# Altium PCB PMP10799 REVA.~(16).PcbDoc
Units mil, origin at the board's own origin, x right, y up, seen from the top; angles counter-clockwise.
Board outline 1968.5 x 1968.5 mil, 4 copper layers (Top Layer, Signal Layer 1, Signal Layer 2, Bottom Layer), stack 85.4 mil thick; 51 components, 27 nets, 127 pads, 65 vias.
Unrouted connection lines stored in the file: 1.
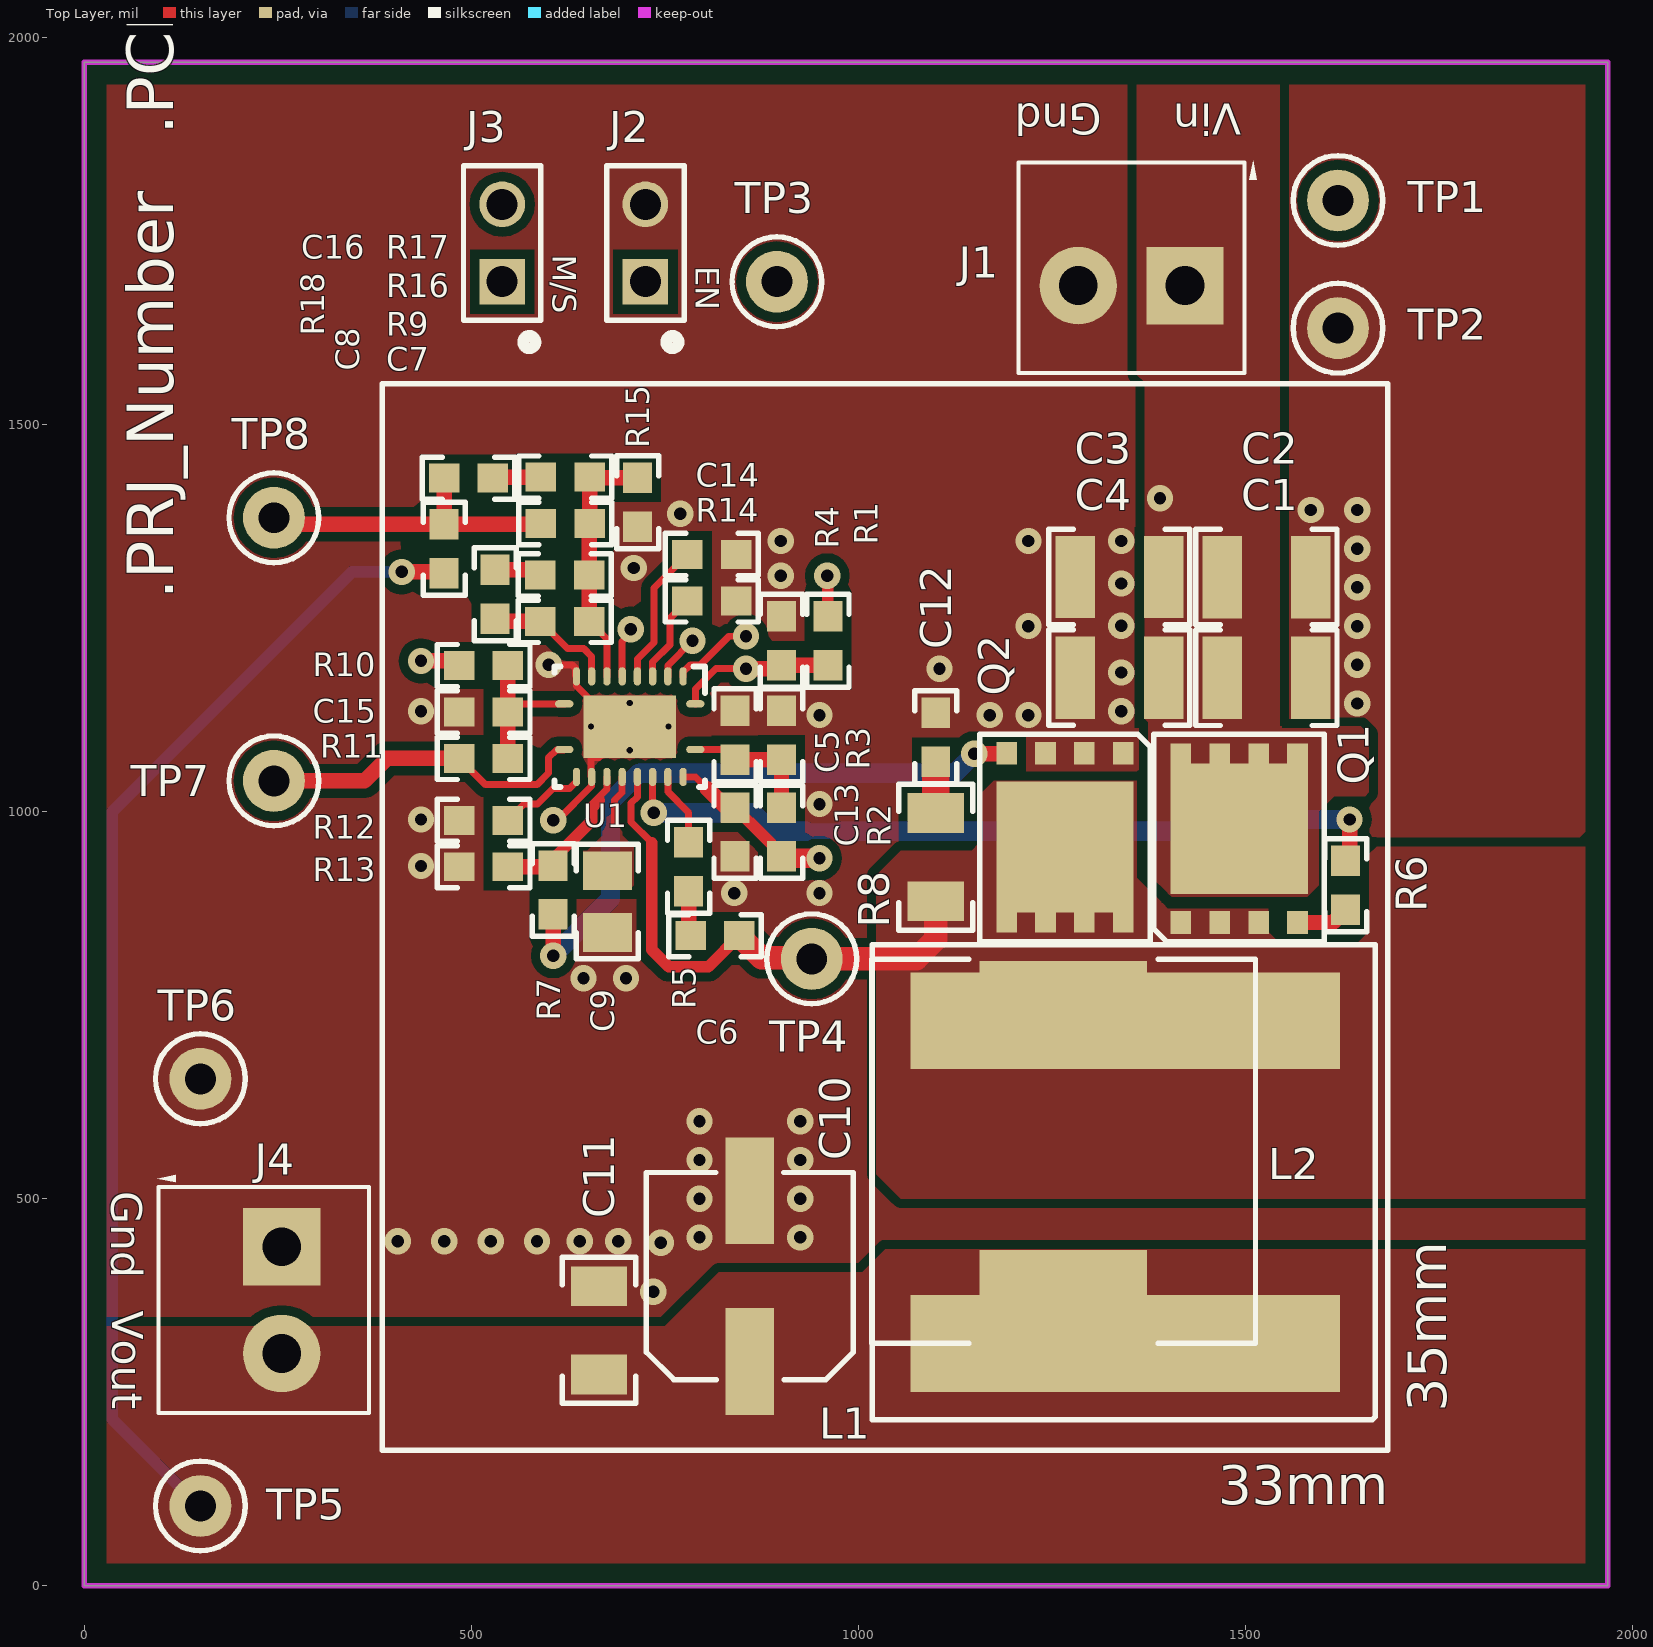
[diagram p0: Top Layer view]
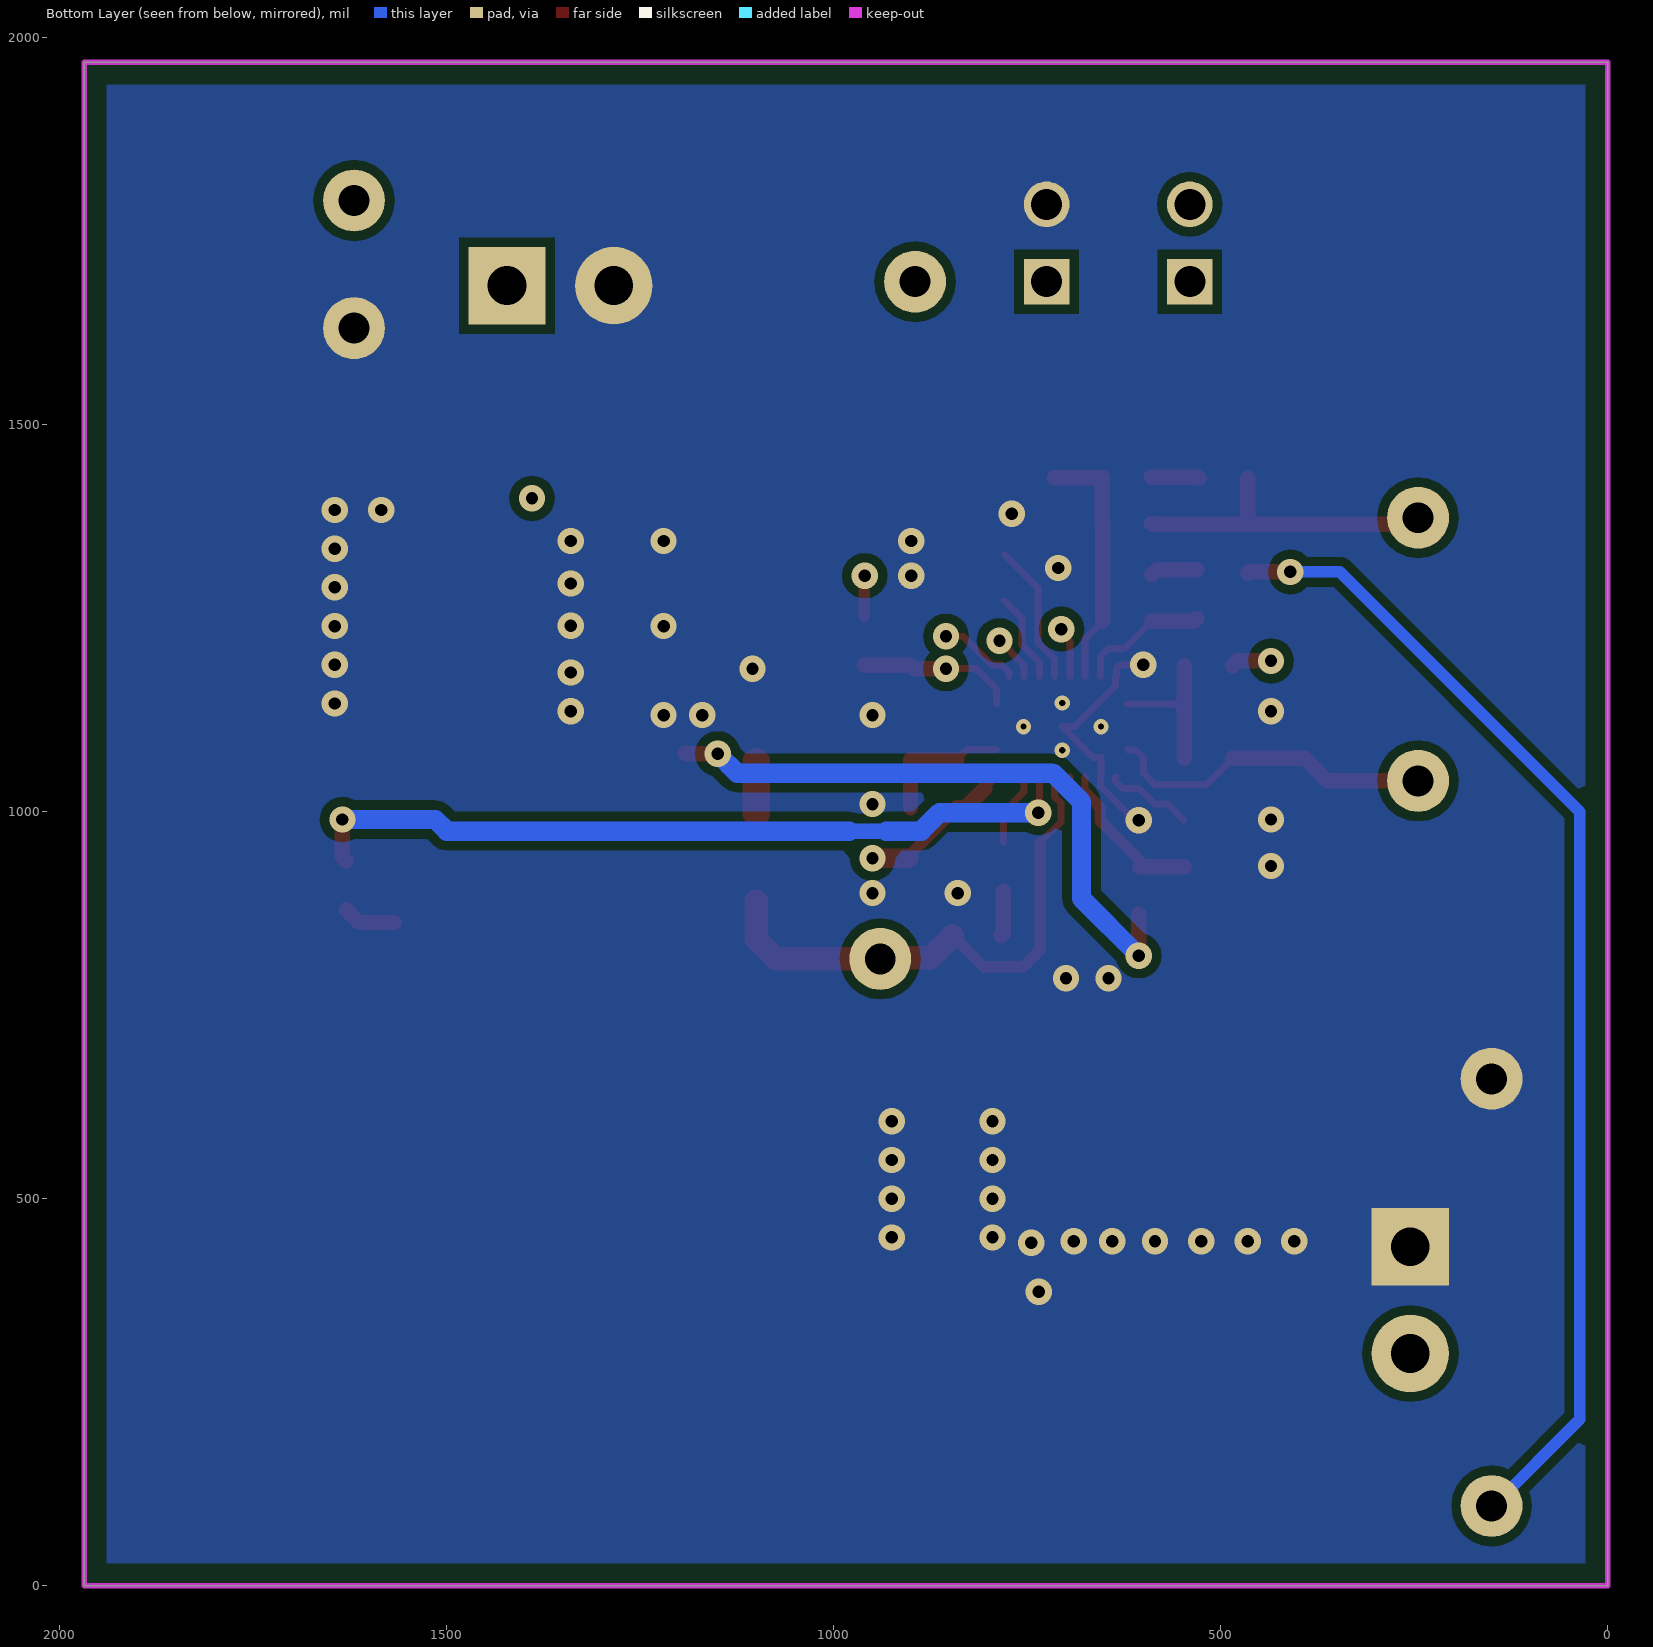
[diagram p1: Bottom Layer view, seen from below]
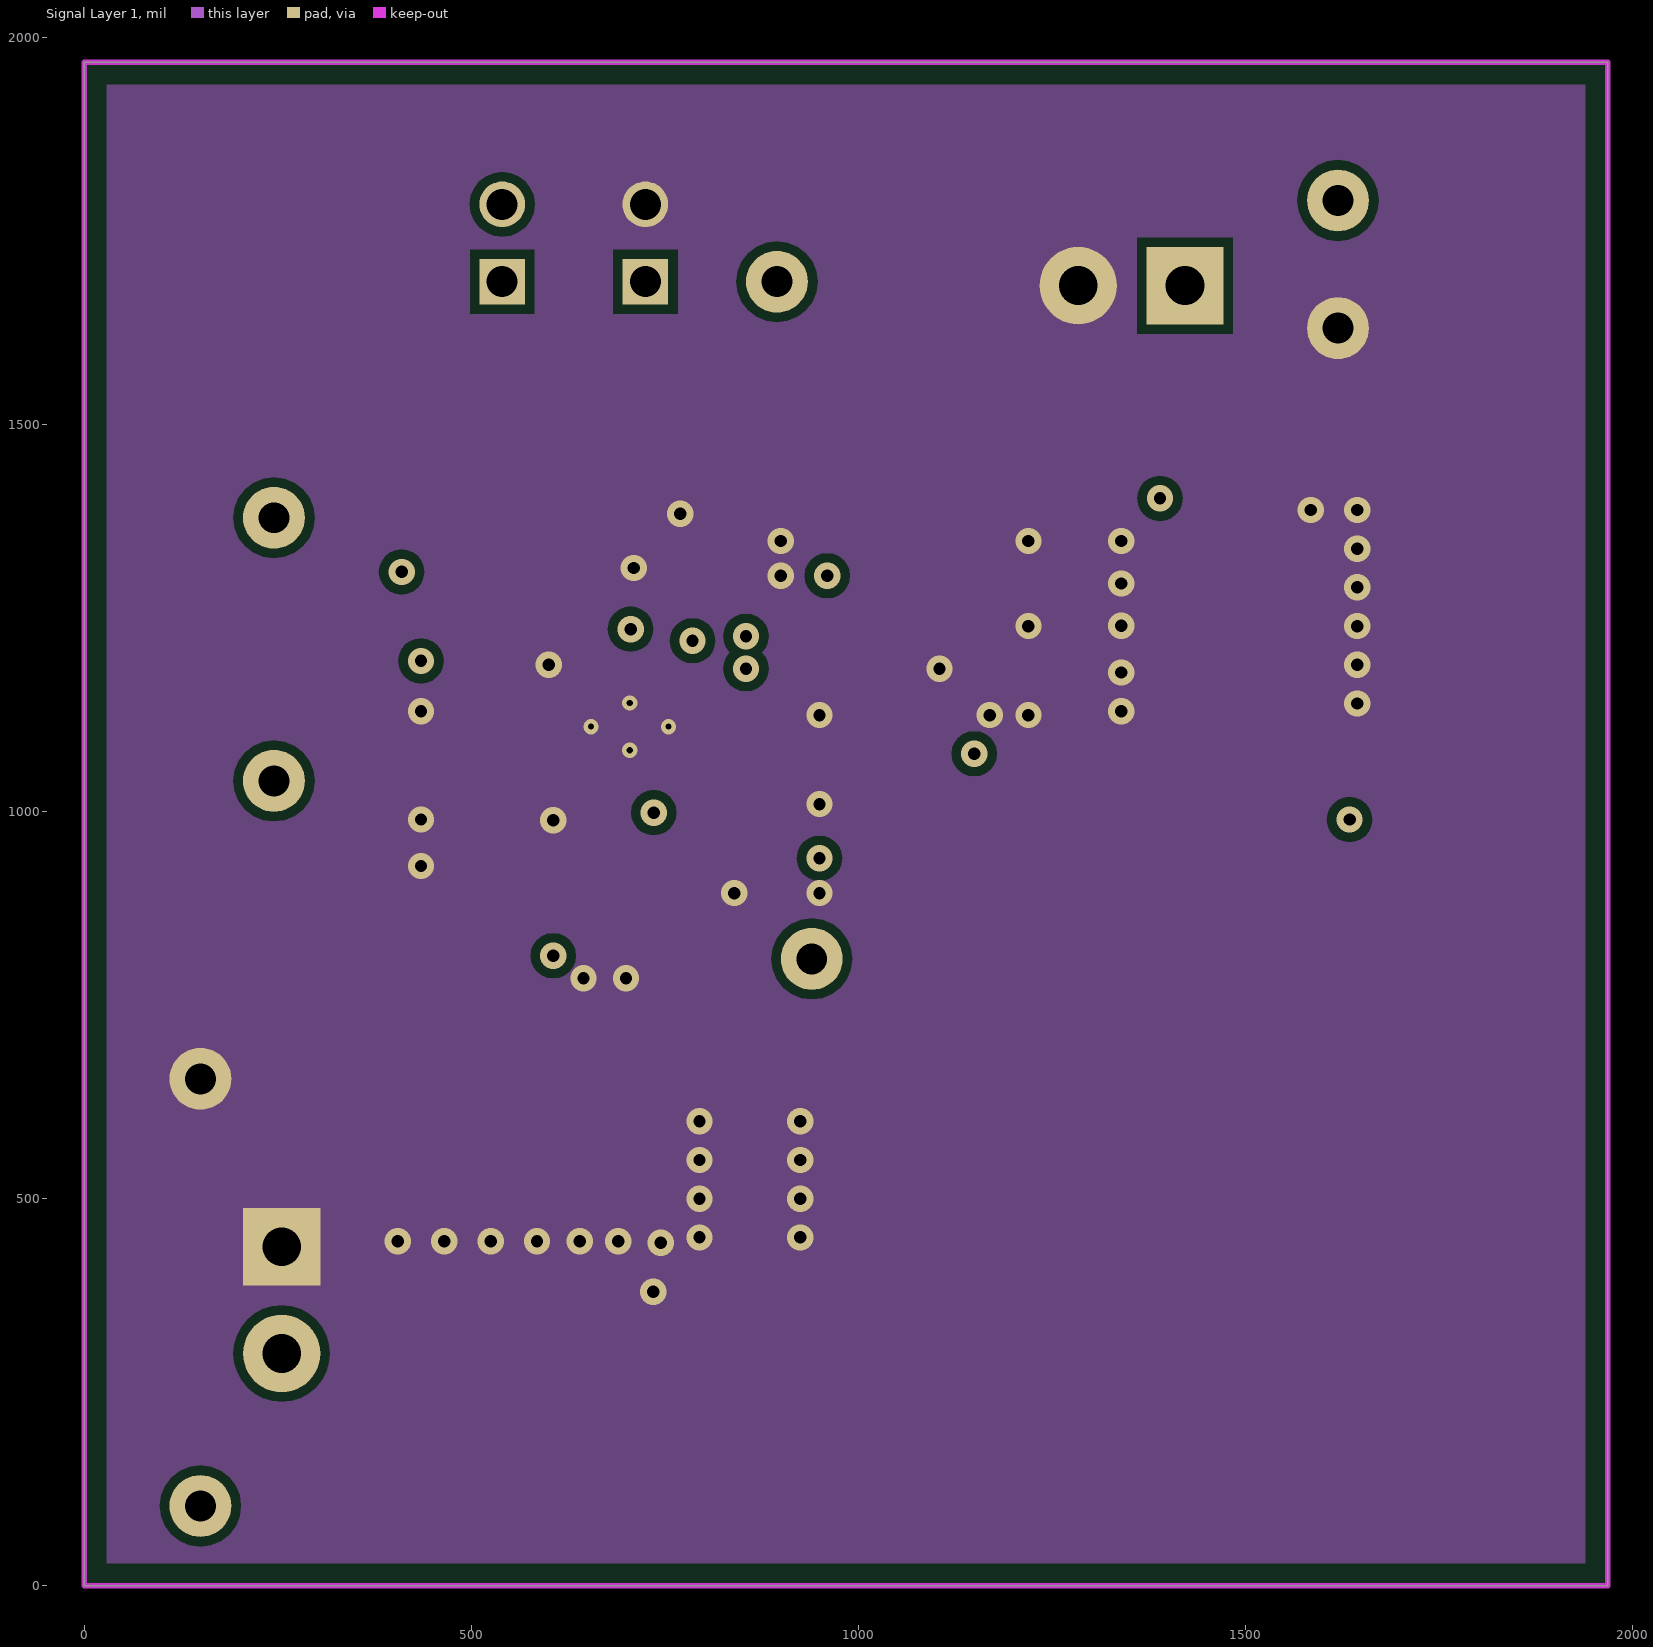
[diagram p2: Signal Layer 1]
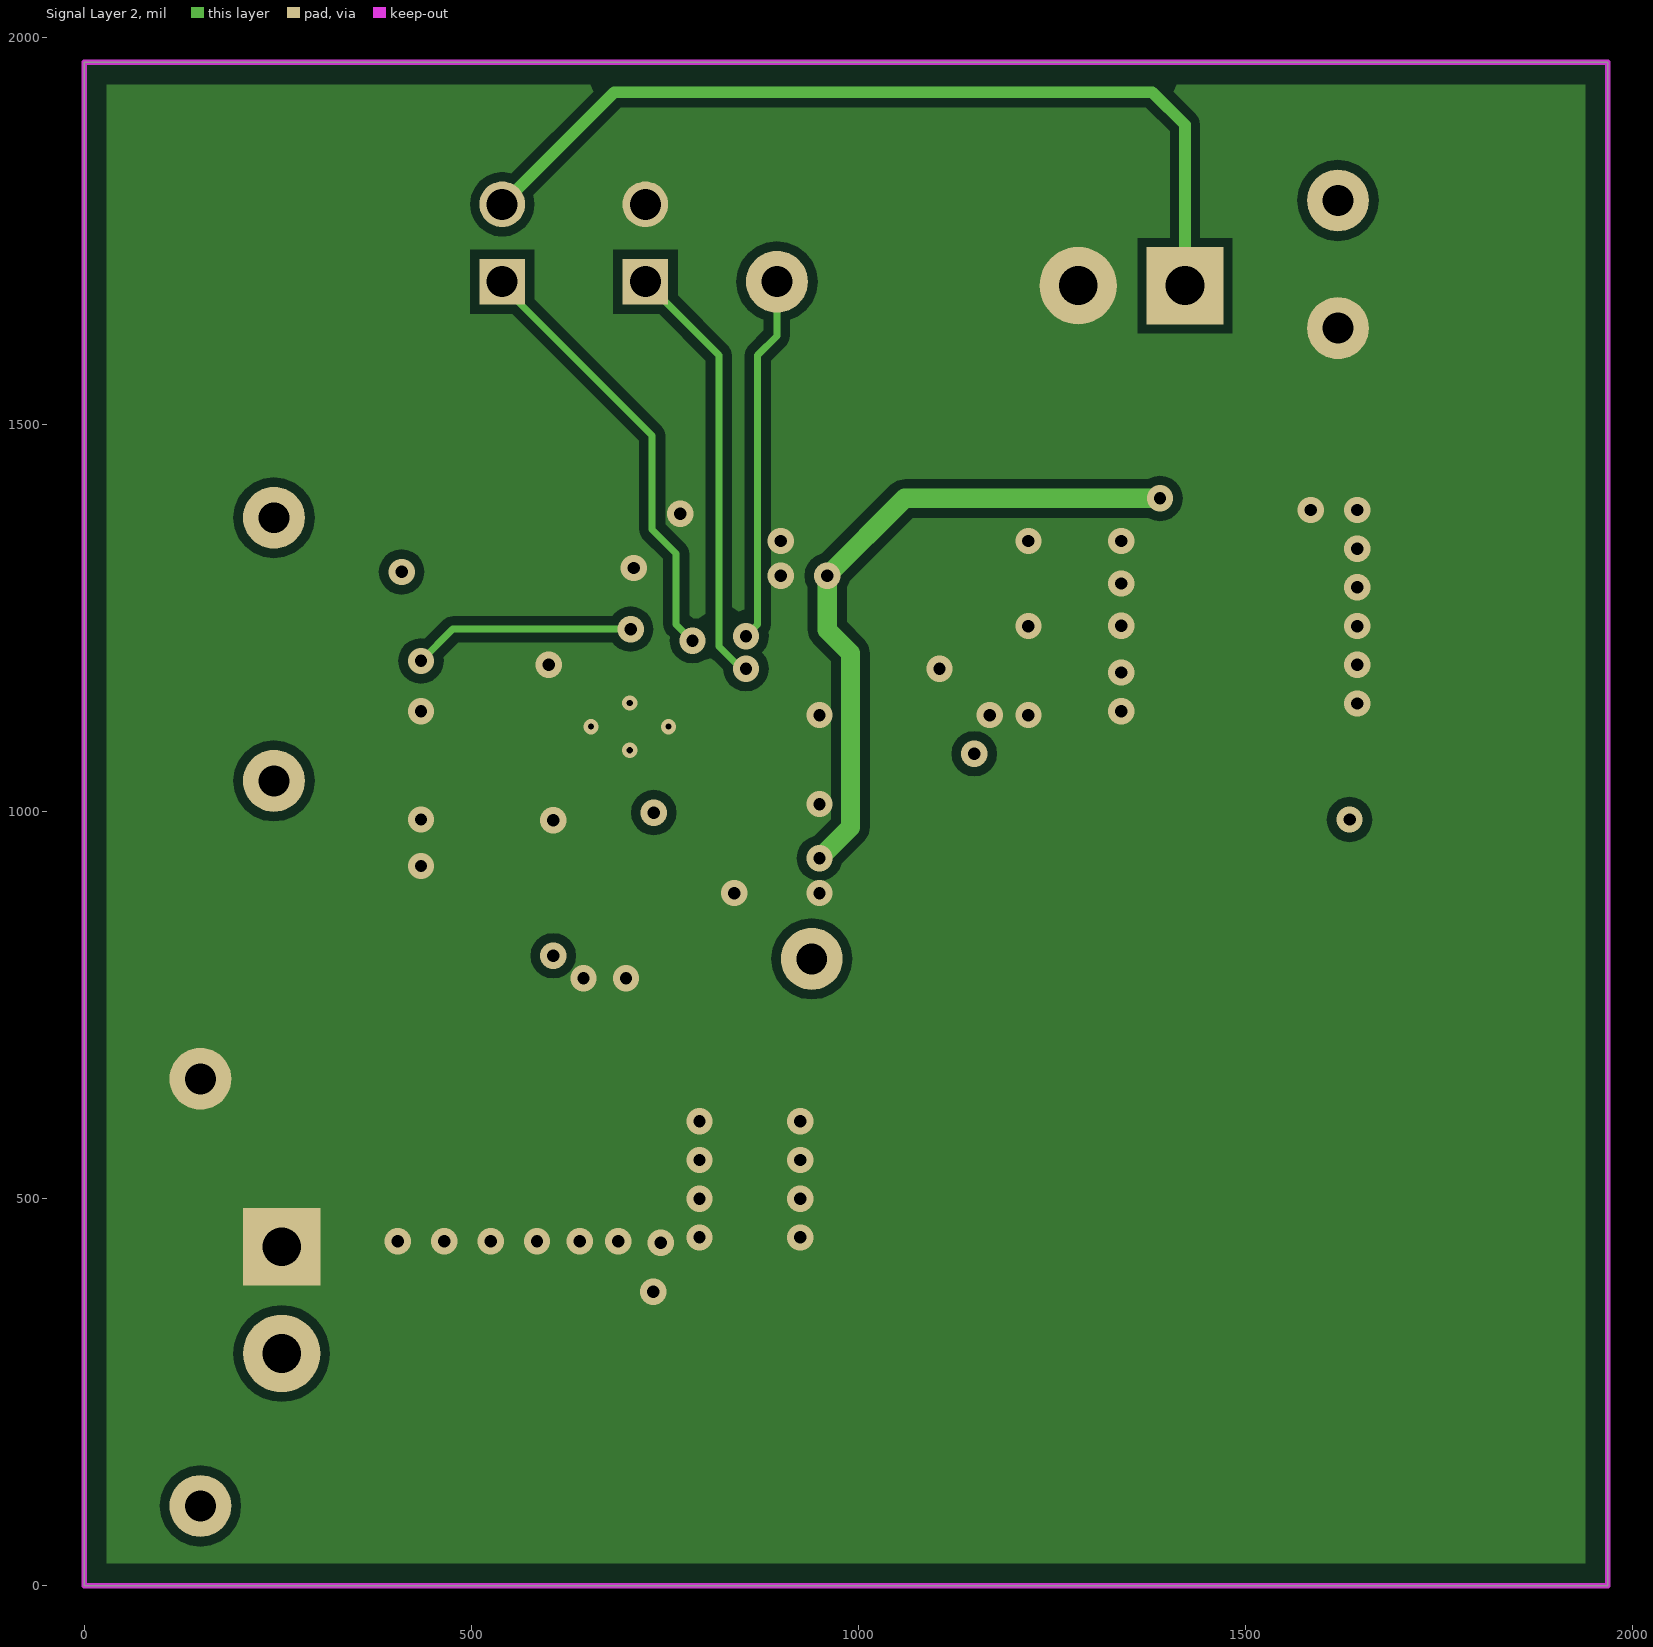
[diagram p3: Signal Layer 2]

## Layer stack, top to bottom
Top Solder: solder mask 0.4, Solder Resist, Dk 3.5
Top Layer: signal copper 2.8
Dielectric1: core 59.2, FR-4, Dk 4.8
Signal Layer 1: signal copper 2.8
Dielectric 3: prepreg 5, Dk 4.2
Signal Layer 2: signal copper 2.8
Dielectric 2: core 10, Dk 4.2
Bottom Layer: signal copper 2.8
Bottom Solder: solder mask 0.4, Solder Resist, Dk 3.5

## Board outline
0,0 1968.5,0 1968.5,1968.5 0,1968.5

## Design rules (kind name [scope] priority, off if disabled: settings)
AcuteAngle [All] p1: minimum=4.50000000000000E+0001 checktracksonly=FALSE
AssemblyTestPointUsage [All] p1: valid=2
Clearance Clearance_Keepouts [((IsTrack Or IsArc) And Not InPoly) And IsFree and IsKeepOut vs ((IsTrack Or IsArc) And Not InPoly) And IsFree and IsKeepOut] p1: gap=0
Clearance Clearance_BoardEdge_MountingHoles [OnCopper and InComponentClass('Mounting Holes') vs IsKeepOut] p2: gap=25
Clearance Clearance_BoardEdge_Poly [OnCopper and InPoly vs IsKeepOut] p3: gap=25
Clearance Clearance_BoardEdge [OnCopper and Not InComponentClass('Logo') and not InComponentClass('FiducialMark') and not InRegion(1000,500,4000,800) and Not IsKeepout vs IsKeepOut] p4: gap=25
Clearance Clearance_Poly [InPolygon] p5: gap=12
Clearance [All] p6: gap=7.87
ComponentClearance ComponentClearance_MountingHoles_FiducialMarks [InComponentClass('Mounting Holes') vs InComponentClass('FiducialMark')] p1: gap=50 collisioncheckmode=3 verticalgap=10 showdistances=FALSE
ComponentClearance ComponentClearance_Shunt [InComponentClass('Header') vs InComponentClass('Shunt')] p2: gap=0 collisioncheckmode=3 verticalgap=0 showdistances=FALSE
ComponentClearance ComponentClearance_Logo [InComponentClass('Logo')] p3: gap=50 collisioncheckmode=3 verticalgap=10 showdistances=FALSE
ComponentClearance ComponentClearance_ScrewToNut [(HasFootprint('NY PMS 440 0025 PH')) vs (HasFootprint('Keystone_1902C'))] p4: gap=5 collisioncheckmode=3 verticalgap=10 showdistances=FALSE
ComponentClearance ComponentClearance_MountingHoles [InComponentClass('Mounting Holes')] p5: gap=250 collisioncheckmode=3 verticalgap=100000 showdistances=FALSE
ComponentClearance ComponentClearance_SmallPassives [HasFootprint('0201*') or HasFootprint('0402*') or HasFootprint('0508') or HasFootprint('0603*') or HasFootprint('0612') or HasFootprint('0805*') or HasFootprint('0815*') or HasFootprint('0830*') or HasFootprint('1206*') or HasFootprint('1210*') or HasFootprint('1808*') or HasFootprint('1812*') or HasFootprint('1825*') or HasFootprint('2010*') or HasFootprint('2220*') or HasFootprint('2225*') or HasFootprint('2512*') or HasFootprint('2728*') or HasFootprint('3518*') vs HasFootprint('0201*') or HasFootprint('0402*') or HasFootprint('0508') or HasFootprint('0603*') or HasFootprint('0612') or HasFootprint('0805*') or HasFootprint('0815*') or HasFootprint('0830*') or HasFootprint('1206*') or HasFootprint('1210*') or HasFootprint('1808*') or HasFootprint('1812*') or HasFootprint('1825*') or HasFootprint('2010*') or HasFootprint('2220*') or HasFootprint('2225*') or HasFootprint('2512*') or HasFootprint('2728*') or HasFootprint('3518*')] p6: gap=10 collisioncheckmode=3 verticalgap=10 showdistances=FALSE
ComponentClearance ComponentClearance_THtoSMT [IsThruComponent vs IsSMTComponent] p7: gap=25 collisioncheckmode=3 verticalgap=30 showdistances=FALSE
ComponentClearance ComponentClearance_THtoTH [IsThruComponent vs IsThruComponent] p8: gap=50 collisioncheckmode=3 verticalgap=30 showdistances=FALSE
ComponentClearance [All] p9: gap=20 collisioncheckmode=3 verticalgap=10 showdistances=FALSE
DiffPairsRouting [All] p1: maxlimit=100 minlimit=10 mostfreqgap=10 toplayer_minwidth=15 toplayer_maxwidth=15 toplayer_prefwidth=15 midlayer1_minwidth=15 midlayer1_maxwidth=15 midlayer1_prefwidth=15 midlayer2_minwidth=15 midlayer2_maxwidth=15 midlayer2_prefwidth=15 bottomlayer_minwidth=15 bottomlayer_maxwidth=15 bottomlayer_prefwidth=15 maxuncoupledlength=1000
FabricationTestPointUsage TestPointUsage [All] p1: valid=2 allowmultiple=FALSE
FabricationTestpoint Testpoint [All] p1: side=3 testpointundercomponent=TRUE minsize=40 maxsize=100 preferedsize=60 minholesize=0 maxholesize=40 preferedholesize=32 testpointgrid=1 allowsidetop=TRUE allowsidebottom=TRUE usegrid=TRUE gridtolerance=0.01
FanoutControl Fanout_LCC [IsLCC] p1: bgadir=Out bgaviamode=Centered fanoutstyle=Auto fanoutdirection=Alternating viagrid=1 // Fanout_LCC (Default Rule)
FanoutControl Fanout_BGA [IsBGA] p2: bgadir=Out bgaviamode=Centered fanoutstyle=Auto fanoutdirection=Alternating viagrid=1 // Fanout_BGA (Default Rule)
FanoutControl Fanout_Default [All] p4: bgadir=Out bgaviamode=Centered fanoutstyle=Auto fanoutdirection=Alternating viagrid=1 // Fanout_Default (Default Rule)
FanoutControl Fanout_Small [(CompPinCount < 5)] p5: bgadir=Out bgaviamode=Centered fanoutstyle=Auto fanoutdirection=OutThenIn viagrid=1 // Fanout_Small (Default Rule)
HoleSize [All] p1: absolutevalues=TRUE maxlimit=251 minlimit=8 maxpercent=80.000 minpercent=20.000
MinimumAnnularRing MinimumAnnularRing_ThermalPadVias [IsVia and InAnyComponent] p1: minimumring=5.91
MinimumAnnularRing [All] p2: minimumring=9
MinimumSolderMaskSliver MinimumSolderMaskSliver_Logo [InComponentClass('Logo') vs InComponentClass('Logo')] p1: minsoldermaskwidth=0.7
MinimumSolderMaskSliver [All] p2: minsoldermaskwidth=3.94
PlaneClearance [All] p1: clearance=12
PlaneConnect [All] p1: planeconnectstyle=Direct reliefexpansion=10 reliefentries=4 reliefconductorwidth=10 reliefairgap=10
PolygonConnect [All] p1: connectstyle=Direct reliefconductorwidth=10 reliefentries=4 polygonreliefangle="90 Angle" airgapwidth=10
RoutingVias ThermalPadVias [IsVia and InAnyComponent] p1: holewidth=7.87 width=19.68 viastyle="Through Hole" minholewidth=7.87 minwidth=19.68 maxholewidth=12.99 maxwidth=23.62
RoutingVias [All] p2: holewidth=16 width=34 viastyle="Through Hole" minholewidth=7.87 minwidth=26 maxholewidth=40 maxwidth=65
SilkToBoardRegionClearance [Not ((IsComment or IsDesignator) And (Hide <> 'False')) and not InRegion(1000,500,4000,800)] p1:
SilkToSilkClearance SilkToSilkClearance_Pb-FreeLogo [(HasFootprint('Pb-Free_Overlay_Medium') OR HasFootprint('Pb-Free_Overlay_Small')) vs (HasFootprint('Pb-Free_Overlay_Medium') OR HasFootprint('Pb-Free_Overlay_Small'))] p1: silktosilkclearance=0
SilkToSilkClearance [All] p2: silktosilkclearance=0
SilkToSolderMaskClearance "Silk to Solder Mask Opening" [All] p1: minsilkscreentomaskgap=1 clearancetoexposedcopper=FALSE
SolderMaskExpansion [All] p1: expansion=1.97
UnpouredPolygon [All] p1: allowunpoured=FALSE
Width [All] p1: maxlimit=100 minlimit=6 preferedwidth=10 checkconnectedcopper=TRUE
13 further rules are at their usual default settings.

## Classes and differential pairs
component class Header: J2 J3

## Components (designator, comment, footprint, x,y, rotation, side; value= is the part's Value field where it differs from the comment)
C1 "GRM32ER61H106MA12" 1210 1527.52,1173.27 r180 top
C2 "GRM32ER61H106MA12" 1210 1527.52,1303.27 r180 top
C3 "GRM32ER61H106MA12" 1210 1337.52,1303.41 r0 top
C4 "GRM32ER61H106MA12" 1210 1337.52,1173.41 r0 top
C5 "C1608X7R1H102K" 0603 840.91,1098.98 r90 top
C6 "C1608X7R1H104K" 0603 815,840 r180 top
C7 "C1608C0G1H330J" 0603 620.91,1246.1 r180 top
C8 "C1608C0G1E472J" 0603 530.91,1281.1 r270 top
C9 "GRM21BR71C475KA73L" 0805_HV 675.91,883.98 r270 top
C10 "16SVPF180M" SM_RADIAL_6.3AMM 860,400 r90 top
C11 "GRM31CR71C106MAC7" 1206 665,330 r90 top
C12 "C1608X7R1H102K" 0603 1100.22,1096.4 r90 top
C13 "C1608X7R1H104K" 0603 840.91,973.98 r90 top
C14 "C1608X7R1H333K" 0603 810.91,1332.52 r0 top
C15 "C1608X5R1C105K" 0603 515.91,1128.98 r180 top
C16 "C1608C0G1H152J" 0603 496.46,1431.1 r180 top
J1 "ED555/2DS" TERM_BLK_ED555-2DS 1422.3,1680 r180 top
J2 "PEC02SAAN" CONN_PEC02SAAN 725,1735 r90 top
J3 "PEC02SAAN" CONN_PEC02SAAN 540,1735 r90 top
J4 "ED555/2DS" TERM_BLK_ED555-2DS 255,438 r270 top
L1 "XAL1510" XAL1510 1345.22,521.4 r270 top
L2 "MSS1210-103ME" MSS1210 1265.22,561.4 r270 top
Q1 "CSD18503Q5A" TRANS_NexFET_Q5A 1492.2,966.28 r90 top
Q2 "CSD18503Q5A" TRANS_NexFET_Q5A 1267.2,966.28 r270 top
R1 "CRCW0603100KFKEA" 0603 960.91,1221.1 r270 top
R2 "CRCW0603301KFKEA" 0603 900.91,973.98 r270 top
R3 "CRCW060315K0FKEA" 0603 900.91,1098.98 r270 top
R4 "CRCW060310K0FKEA" 0603 900.91,1221.1 r90 top
R5 "CRCW06034R70JNEA" 0603 780.91,928.98 r90 top
R6 "CRCW06034R70JNEA" 0603 1630,905 r90 top
R7 "CRCW06034R70JNEA" 0603 605.91,898.98 r90 top
R8 "ERJ-8RQF2R7V" 1206 1100.22,941.4 r270 top
R9 "CRCW060315K0FKEA" 0603 620.91,1306.1 r0 top
R10 "CRCW060310K0FKEA" 0603 515.91,1188.98 r0 top
R11 "CRCW060310K0FKEA" 0603 515.91,1068.98 r0 top
R12 "CRCW06037K87FKEA" 0603 515.91,988.98 r0 top
R13 "" 0603 515.91,928.98 r0 top
R14 "CRCW060331K6FKEA" 0603 810.91,1272.52 r180 top
R15 "CRCW06032K61FKEA" 0603 715,1400 r270 top
R16 "CRCW060349K9FKEA" 0603 621.46,1372.56 r0 top
R17 "CRCW06032K61FKEA" 0603 621.46,1432.56 r0 top
R18 "CRCW0603100RFKEA" 0603 465,1340 r270 top
TP1 "5000" Keystone5000 1620,1790 r0 top
TP2 "5001" Keystone5001 1620,1625 r0 top
TP3 "5000" Keystone5000 895,1685 r0 top
TP4 "5000" Keystone5000 940,810 r0 top
TP5 "5000" Keystone5000 150,103 r0 top
TP6 "5001" Keystone5001 150,655 r0 top
TP7 "5000" Keystone5000 245,1040 r0 top
TP8 "5000" Keystone5000 245,1380 r0 top
U1 "TPS40170RGY" RGY0020A 704.84,1110.04 r270 top

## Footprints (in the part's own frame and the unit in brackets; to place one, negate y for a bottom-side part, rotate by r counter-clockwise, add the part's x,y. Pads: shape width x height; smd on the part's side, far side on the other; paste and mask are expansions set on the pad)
0603 [mm] "0603 from SM-752 data"
  rect 1x0.95 smd: 1(-0.8,0) 2(0.8,0)
  silkscreen extent -1.52,-0.69 1.52,0.69, body extent -0.87,-0.47 0.87,0.47, height 0.85
0805_HV [mil] "0805 with 30mil clearance between pads"
  rect 50x63 smd: 1(-40,0) 2(40,0)
  silkscreen extent -74,-40 74,40, body extent -43,-29 43,29, height 43
1206 [mm] "1206 from SM-752 data"
  rect 1.3x1.85 smd: 1(-1.45,0) 2(1.45,0)
  silkscreen extent -2.4,-1.21 2.4,1.21, body extent -1.7,-0.9 1.7,0.9, height 1.35
1210 [mm] "1210 from SM-752 data"
  rect 1.3x2.7 smd: 1(-1.45,0) 2(1.45,0)
  silkscreen extent -2.32,-1.57 2.32,1.57, body extent -1.7,-1.35 1.7,1.35, height 1.35
CONN_PEC02SAAN [mm] "SULLINS"
  rect 1.5x1.5 hole 1.016: 1(-1.27,0)
  round 1.5 hole 1.016: 2(1.27,0)
  silkscreen extent -3.45,-1.27 2.54,1.27, body extent -2.54,-1.27 2.54,1.27, height 8.38
Keystone5000 [mil] "For Keystone 500x miniature loop terminals"
  round 80 hole 40: 1(0,0)
  silkscreen extent -58,-58 58,58, body extent -49,-49 49,49, height 182
Keystone5001 [mil] "For Keystone 500x miniature loop terminals"
  round 80 hole 40: 1(0,0)
  silkscreen extent -58,-58 58,58, body extent -49,-49 49,49, height 182
MSS1210 [mm] "Coilcraft MSS1210 series"
  rect 3x5.5 smd: 1(-4.75,0) 2(4.75,0)
  silkscreen extent -6.3,-6.3 6.3,6.3, body extent -6.15,-6.15 6.15,6.15, height 10.2
RGY0020A [mm] "QFN, 20-Leads, Body 4.5x3.5mm, Pitch 0.5mm, Thermal Pad 3.05x2.05mm, TI Recommended"
  oval 0.24x0.6 smd: 1(-0.75,2.15) 10(-0.75,-2.15) 11(0.75,-2.15) 20(0.75,2.15)
  oval 0.6x0.24 smd: 2(-1.65,1.75) 3(-1.65,1.25) 4(-1.65,0.75) 5(-1.65,0.25) 6(-1.65,-0.25) 7(-1.65,-0.75) 8(-1.65,-1.25) 9(-1.65,-1.75) 12(1.65,-1.75) 13(1.65,-1.25) 14(1.65,-0.75) 15(1.65,-0.25) 16(1.65,0.25) 17(1.65,0.75) 18(1.65,1.25) 19(1.65,1.75)
  rect 2.05x3.05 smd paste-1.025: 21(0,0)
  silkscreen extent -1.97,-2.47 1.97,2.47, body extent -1.83,-2.33 1.83,2.32, height 1.01
SM_RADIAL_6.3AMM [mm] "Nichicon 6.3x5.8"
  rect 3.5x1.6 smd: 1(-2.8,0) 2(2.8,0)
  silkscreen extent -3.4,-3.4 3.4,3.4, body extent -3.41,-3.41 3.41,3.41, height 6.1
TERM_BLK_ED555-2DS [mil]
  rect 100x100 hole 50: 1(0,0)
  round 100 hole 50: 2(138,0)
  silkscreen extent -93,-161 215,113, body extent -69,-150 207,106, height 323
TRANS_NexFET_Q5A [mm] "TI recommended land pattern (nominal) M0139-01"
  rect 0.75x0.675 smd paste-0.1 mask+0.051: 1(-2.776,1.917) 2(-2.776,0.639) 3(-2.776,-0.639) 4(-2.776,-1.917)
  rect 0.655x0.675 smd paste-0.1 mask+0.051: 5(2.776,-1.917) 6(2.776,-0.639) 7(2.776,0.639) 8(2.776,1.917)
  rect 4.295x4.51 smd paste-2.2 mask+0.051: 9(0.301,0)
  silkscreen extent -3.4,-2.8 3.4,2.8, body extent -3.05,-2.5 3.05,2.5, height 1.11
XAL1510 [mm] "COILCRAFT"
  rect 3.18x14.1 smd: 1(-5.3,0) 2(5.3,0)
  silkscreen extent -7.8,-8.3 7.8,8.2, body extent -7.7,-8.2 7.7,8.2, height 11

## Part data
C1 C2 C3 C4: library part C3225X7R1E106M, "CAP, CERM, 10uF, 50V, +/-20%, X5R, 1210"
C5 C12: "CAP, CERM, 1000 pF, 50 V, +/- 10%, X7R, 0603"
C6 C13: "CAP, CERM, 0.1uF, 50V, +/-10%, X7R, 0603"
C7: "CAP, CERM, 33 pF, 50 V, +/- 5%, C0G/NP0, 0603"
C8: "CAP, CERM, 4700 pF, 25 V, +/- 5%, C0G/NP0, 0603"
C9: "CAP, CERM, 4.7 µF, 16 V, +/- 10%, X7R, 0805"
C10: library part 16SVP39M, "CAP, OS-CON, 180 µF, 16 V, +/- 20%, 0.022 ohm, 6.3x5.9 SMD"
C11: library part GRM31CR71C106KAC7L, "CAP, CERM, 10 µF, 16 V, +/- 20%, X7R, 1206"
C14: library part C1608X7R1H473K, "CAP, CERM, 0.033 µF, 50 V, +/- 10%, X7R, 0603"
C15: "CAP, CERM, 1 µF, 16 V, +/- 10%, X5R, 0603"
C16: "CAP, CERM, 1500 pF, 50 V, +/- 5%, C0G/NP0, 0603"
J1 J4: "Terminal Block, 6A, 3.5mm Pitch, 2-Pos, TH"
J2 J3: "Header, 100mil, 2x1, Tin, TH"
L1: library part XAL1510-103MEB, "Inductor, open, SMD"
L2: "Inductor, Shielded, Ferrite, 10 µH, 10 A, 0.014 ohm, SMD"
Q1 Q2: library part CSD18501Q5A, "MOSFET, N-CH, 40 V, 3.4 milliohm, SON 5x6mm"
R1: "RES, 100 k, 1%, 0.1 W, 0603"
R2: "RES, 301 k, 1%, 0.1 W, 0603"
R3 R9: "RES, 15.0 k, 1%, 0.1 W, 0603"
R4 R10 R11: "RES, 10.0 k, 1%, 0.1 W, 0603"
R5 R6 R7: "RES, 4.7, 5%, 0.1 W, 0603"
R8: "RES, 2.70, 1%, 0.25 W, 1206"
R12: "RES, 7.87 k, 1%, 0.1 W, 0603"
R13: library part CRCW06037K87FKEA, "RES, open, 0603"
R14: "RES, 31.6 k, 1%, 0.1 W, 0603"
R15 R17: "RES, 2.61 k, 1%, 0.1 W, 0603"
R16: "RES, 49.9 k, 1%, 0.1 W, 0603"
R18: "RES, 100, 1%, 0.1 W, 0603"
TP1 TP3 TP4 TP5 TP7 TP8: "Test Point, Miniature, Red, TH"
TP2 TP6: "Test Point, Miniature, Black, TH"
U1: "4.5-v to 60-v wide-input synchronous PWM buck controller, RGY0020A"

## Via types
v1: diameter 34, hole 16, Top Layer to Bottom Layer, 61 vias
v2: diameter 19.68, hole 7.87, Top Layer to Bottom Layer, 4 vias

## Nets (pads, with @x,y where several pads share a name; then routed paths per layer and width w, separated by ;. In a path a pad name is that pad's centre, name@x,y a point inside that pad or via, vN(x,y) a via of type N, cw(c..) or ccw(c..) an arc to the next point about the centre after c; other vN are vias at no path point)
GND: C1.1 C2.1 C3.1 C4.1 C5.2 C9.2 C10.2 C11.2 C12.2 C13.1 C14.2 C15.2 J1.2 J2.2 J4.1 Q2.1 Q2.2 Q2.3 R3.1 R4.2 R12.1 R13.1 R14.1 R15.2 TP2.1 TP6.1 U1.9 U1.13 U1.21 | length 321.8
  Top Layer w9: v1(600,1190) 630,1190 635,1185 635,1175.94 U1.9 635.94,1162.76 688.66,1110.04 U1.21 664.8,1070 655,1070 655,1045.71 U1.13 655.63,1033.5 611.11,988.98 v1(605.91,988.98)
  other v1: 735,380 745,443.31 405,445 465,445 525,445 585,445 640,445 690,445 795,450 925,450 795,500 925,500 795,550 925,550 795,600 925,600 645,785 700,785 840,895 950,895 435,930 435,990 950,1010 950,1125 1170,1125 1220,1125 435,1130 1340,1130 1645,1140 1340,1180 1105,1185 1645,1190 1220,1240 1340,1240.41 1645,1240 1645,1290 1340,1295 900,1305 710,1315 1645,1340 900,1350 1220,1350 1340,1350 770,1385 1585,1390 1645,1390
  other v2: 704.84,1079.53 654.65,1110.04 755.04,1110.04 704.84,1140.55
NetC1_2: C1.2 C2.2 C3.2 C4.2 C13.2 J1.1 J3.2 Q1.5 Q1.6 Q1.7 Q1.8 Q1.9 R1.1 R2.2 TP1.1 U1.19 | length 2307.4
  Top Layer w9: U1.19 773.82,1045 790,1045 805,1030
  Top Layer w15: C13.2 840.91,1005.34 875.84,970.41 875.96,970.41 900.91,945.47 R2.2 R2.2@903.39,940 ; v1(960,1305) 960.91,1304.09 R1.1
  Top Layer w20: 805,1030 829.53,1005.47 C13.2
  Top Layer w25: R2.2@903.39,940 v1(950,940)
  Signal Layer 2 w15: J3.2 685,1930 1380,1930 1422.3,1887.7 J1.1
  Signal Layer 2 w25: v1(950,940) 990,980 990,1205 960,1235 v1(960,1305) 1060,1405 v1(1390,1405)
NetC5_1: C5.1 R2.1 R3.2 U1.20 | length 178.8
  Top Layer w9: U1.20 827.87,1080.51 C5.1
  Top Layer w20: C5.1 R3.2 R2.1
NetC6_1: C6.1 L1.1 L2.1 Q1.1 Q1.2 Q1.3 Q2.5 Q2.6 Q2.7 Q2.8 Q2.9 R8.2 TP4.1 U1.16 | length 702.3
  Top Layer w9: U1.16 714.68,1019.3 706.53,1011.14 706.53,986.81 733.34,960
  Top Layer w15: 733.34,960 733.34,821.66 755,800 806.5,800 C6.1
  Top Layer w30: C6.1 875.04,811.46 938.54,811.46 TP4.1 1075,810 1100.22,835.22 R8.2
NetC6_2: C6.2 R5.1 | length 58.6
  Top Layer w20: R5.1 780.91,842.6 C6.2
NetC7_1: C7.1 R9.2 R15.1 R16.2 R17.2 U1.7 | length 329.8
  Top Layer w9: C7.1 675.31,1223.19 U1.7
  Top Layer w20: C7.1 652.4,1372.01 R16.2 R17.2 654.02,1431.5 R15.1
NetC7_2: C7.2 C8.2 U1.8 | length 170.8
  Top Layer w9: C7.2 624.41,1211.1 645.35,1211.1 655.63,1200.83 U1.8
  Top Layer w20: C8.2 534.41,1246.1 C7.2
NetC8_1: C8.1 R9.1 | length 61.2
  Top Layer w20: C8.1 582.91,1312.6 R9.1
NetC9_1: C9.1 U1.15 | length 64.2
  Top Layer w9: 685,985 685,1015 695,1025 U1.15
NetC10_1: C10.1 C11.1 J4.2 L1.2 L2.2 R18.2 TP5.1 | length 1503.4
  Top Layer w20: v1(410,1310) 463.5,1310 R18.2
  Bottom Layer w15: TP5.1 148,103 36,215 36,1000 346,1310 v1(410,1310)
NetC12_1: C12.1 R8.1 | length 66.4
  Top Layer w35: R8.1 C12.1
NetC14_1: C14.1 U1.5 | length 184.3
  Top Layer w9: U1.5 714.68,1197.61 735.91,1218.83 735.91,1289.02 C14.1
NetC15_1: C15.1 R10.2 R11.2 U1.10 | length 197.2
  Top Layer w9: C15.1 557.99,1139.57 U1.10
  Top Layer w20: R11.2 C15.1 R10.2
NetC16_1: C16.1 R17.1 | length 62.6
  Top Layer w20: C16.1 529.41,1432.56 R17.1
NetC16_2: C16.2 R16.1 R18.1 TP8.1 | length 408.5
  Top Layer w20: TP8.1 253.5,1371.5 R18.1 ; C16.2 R18.1 R18.1 ; R16.1 588.9,1371.5 R18.1
NetJ2_1: J2.1 R1.2 R4.1 U1.1 | length 760.6
  Top Layer w9: U1.1 790,1140.08 790,1158.62 816.38,1185 v1(855,1185)
  Top Layer w20: v1(855,1185) 896.3,1185 R4.1 R1.2
  Signal Layer 2 w9: J2.1 820,1590 820,1213.66 848.66,1185 v1(855,1185)
NetJ3_1: J3.1 U1.3 | length 625.1
  Top Layer w9: U1.3 754.06,1189.25 v1(785.91,1221.1)
  Signal Layer 2 w9: J3.1 540,1680 733.7,1486.3 733.7,1364.84 764.75,1333.79 764.75,1242.26 v1(785.91,1221.1)
NetQ1_4: Q1.4 R6.1 | length 69.1
  Top Layer w20: Q1.4 1613.47,856.98 R6.1
NetQ2_4: Q2.4 R7.1 | length 821.1
  Top Layer w20: v1(605.91,813.98) R7.1 ; v1(1150,1075) 1191.13,1075 Q2.4
  Bottom Layer w25: v1(605.91,813.98) 680,888.07 680,1013.35 715.96,1049.31 717.36,1049.31 718.05,1050 1125,1050 v1(1150,1075)
NetR5_2: R5.2 U1.18 | length 95.7
  Top Layer w9: U1.18 754.06,1025.95 780.91,999.09 R5.2
NetR6_2: R6.2 U1.17 | length 1017.6
  Top Layer w9: U1.17 734.37,1000.51 v1(735.91,998.98)
  Top Layer w20: R6.2 1635,941.5 v1(1635,990)
  Bottom Layer w20: 932.15,975 980,975
  Bottom Layer w25: v1(735.91,998.98) 863.23,998.98 887.2,975 932.15,975 ; 980,975 1500,975 1515,990 v1(1635,990)
NetR7_2: R7.2 R13.2 U1.14 | length 202.5
  Top Layer w9: 665.12,1014.88 665.12,1019.12 675.31,1029.32 U1.14
  Top Layer w15: R7.2@604.41,928.98 604.41,937.2 655.5,988.29 655.5,1005.26 665.12,1014.88
  Top Layer w20: R13.2 R7.2@604.41,928.98
NetR10_1: R10.1 U1.6 | length 405.5
  Top Layer w9: U1.6 695,1220.2 705.91,1231.1 v1(705.91,1236.1)
  Top Layer w20: v1(435,1195) 478.39,1195 R10.1
  Signal Layer 2 w9: v1(435,1195) 476.1,1236.1 v1(705.91,1236.1)
NetR11_1: R11.1 TP7.1 U1.11 | length 431.8
  Top Layer w9: R11.1 518.39,1035 585,1035 600,1050 600,1070 610,1080 619.69,1080 U1.11
  Top Layer w20: TP7.1 362.05,1040 391.02,1068.98 R11.1
NetR12_2: R12.2 U1.12 | length 115.3
  Top Layer w9: R12.2 568.43,1010 585.39,1010 605.39,1030 626.81,1030 635.94,1039.13 U1.12
NetR14_2: R14.2 U1.4 | length 116.2
  Top Layer w9: U1.4 734.37,1193.43 756.53,1215.59 756.53,1249.64 R14.2
NetTP3_1: TP3.1 U1.2 | length 580.7
  Top Layer w9: U1.2 773.74,1180.63 783.11,1190 796.34,1190 833.22,1226.87 v1(855,1226.87)
  Signal Layer 2 w9: v1(855,1226.87) 870,1241.87 870,1590 895,1615 TP3.1

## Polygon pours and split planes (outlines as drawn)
GND on Top Layer "Top Layer-No Net 5" (solid, remove dead copper, pour order 22): 0,0 0,1968.5 1968.5,1968.5 1968.5,0
NetC10_1 on Top Layer "Top Layer-No Net 4" (solid, remove dead copper, pour order 14): 1968.5,435 1035,435 1005,405 825,405 820,405 750,335 360,335 0,335 0,0 1968.5,0
NetC6_1 on Top Layer "Top Layer-No Net 3" (solid, remove dead copper, pour order 12): 1355,1040 1180,1040 1175,1040 1155,1020 1155,960 1155,958.52 1146.48,950 1085,950 1055,950 1045,940 1023.09,918.09 1023.09,665 1023.09,531.91 1050,505 1055,500 1620,500 1963.5,500 1968.5,505 1968.5,955 1670,955 1660,945 1658.54,943.54 1658.54,843.98 1658.54,843.54 1645,830 1550,830 1545,830 1530,845 1530,870 1530,875 1470,875 1400,875 1360,915 1360,1040
NetC1_2 on Top Layer "Top Layer-No Net 2" (solid, remove dead copper, pour order 10): 1405,890 1375,920 1375,965 1375,1135 1425,1135 1425,890
NetC1_2 on Top Layer "Top Layer-No Net 1" (solid, remove dead copper, pour order 8): 1360,1970 1360,1565 1370,1555 1370,1225 1370,1120 1390,1100 1400,1090 1400,1086.36 1400,895 1405,890 1580,890 1595,905 1595,1000 1610,1015 1615,1020 1650,1020 1655,1020 1660,1025 1660,1090 1660,1100 1650,1110 1649.72,1110.28 1545,1110.28 1545,1180 1545,1490 1545,1968.5
NetC9_1 on Top Layer "Top Layer-No Net" (solid, remove dead copper, pour order 4): 645,950 650,950 670,970 670,985 670,995 680,1005 685,1010 685,1015 690,1020 695,1025 695,970 710,955 710,950 710,905 705,900 645,900
GND on Bottom Layer "Bottom Layer-No Net" (solid, remove dead copper, pour order 16): 0,0 0,1968.5 1968.5,1968.5 1968.5,0
GND on Signal Layer 2 "Signal Layer 2-No Net" (solid, remove dead copper, pour order 18): 0,0 0,1968.5 1968.5,1968.5 1968.5,0
GND on Signal Layer 1 "Signal Layer 1-No Net" (solid, remove dead copper, pour order 20): 0,0 0,1968.5 1968.5,1968.5 1968.5,0

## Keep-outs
Keep-Out Layer:
  the board outline again, w7.01
  text ".Layer_Name" at 577,-858.49 h60

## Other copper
Top Layer:
  text ".Layer_Name" at 577,-858.49 h60
Bottom Layer:
  text ".Layer_Name" at 577,-858.49 h60

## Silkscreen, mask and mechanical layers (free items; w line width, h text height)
Top Overlay:
  lines w7.01: 385,175 385,1552.95 1684.21,1552.95 1684.21,175 385,175
  text "Gnd" at 1315,1915 h40 r180
  text "Vin" at 1495,1915 h40 r180
  text ".PCB_Rev" at 115,1875 h60 r90
  text "M/S" at 605,1720 h30 r270
  text "EN" at 790,1705 h30 r270
  text ".PRJ_Number" at 115,1275 h60 r90
  text "Gnd" at 35,510 h40 r270
  text "Vout" at 36,355 h40 r270
  text "35mm" at 1760,225 h50 r90
  text "33mm" at 1465,105 h50
  text ".Layer_Name" at 577,-858.49 h60
Bottom Overlay:
  text ".Layer_Name" at 577,-858.49 h60
Top Paste:
  text ".Layer_Name" at 577,-858.49 h60
Bottom Paste:
  text ".Layer_Name" at 577,-858.49 h60
Top Solder:
  text ".Layer_Name" at 577,-858.49 h60
  text ".Layer_Name" at 577,-858.49 h60
Bottom Solder:
  text ".Layer_Name" at 577,-858.49 h60
Drill Guide:
  text ".Layer_Name" at 577,-858.49 h60
M1 Board Outline:
  lines w7.01: 0,0 0,1968.5 1968.5,1968.5 1968.5,0 0,0
  lines w10: 0,0 0,1968.5 1968.5,1968.5 1968.5,0 0,0
  text ".Layer_Name" at 577,-858.49 h60
M2 Board Dimensions:
  rectangle: 0,-275 125,-150
  rectangle: 125,-400 500,-275
  lines w7: 0,-275 1000,-275 ; 125,-400 125,-150 ; 250,-400 250,-150 ; 500,-400 500,-150 ; 750,-400 750,-150 ; 0,-400 1000,-400 1000,-150 0,-150 0,-400
  text ".Layer_Name" at 577,-858.49 h60
M3 3D STEP Top:
  text ".Layer_Name" at 577,-858.49 h60
M4 3D STEP Bottom:
  text ".Layer_Name" at 577,-858.49 h60
M5 Assembly Top:
  lines w10: -292,-930.17 6308,-930.17 ; -292,-726.83 6310,-726.83 ; -292,-523.5 -292,-1133.5 3713,-1133.5 6310,-1133.5 6310,-523.5 -291.5,-523.5 -291.5,-1133.5 1284,-1133.5 ; 2173,-1133.5 2173,-523.5 ; 3440,-726.83 3440,-523.5 ; 4280,-726.83 4280,-523.5 ; 4902,-1140 4902,-937.17
  text "COMPONENTS MARKED 'DNP' SHOULD NOT BE POPULATED." at 1153.5,-318.5 h60
  text "ASSEMBLY VARIANT:" at 1153,-434 h60
  text ".VariantName" at 2189,-434 h60
  text "PCB VIEWED FROM TOP SIDE" at -228.5,-655.67 h60
  text "BOARD #:" at 2248,-655.67 h60
  text ".PRJ_Number" at 2793.5,-655.67 h60
  text "REV:" at 3638,-655.67 h60
  text ".PCB_Rev" at 3929.5,-655.67 h60
  text "SVN REV:" at 4476,-655.67 h60
  text ".VersionControl_RevNumber" at 4982,-655.67 h60
  text "PLOT NAME =" at -228.5,-1064.34 h60
  text ".plot_File_Name" at 577,-1064.34 h60
  text "GENERATED    :" at 2250,-1064.34 h60
  text ".Print_Date" at 3119.5,-1064.34 h60
  text ".Print_Time" at 3848.5,-1064.34 h60
  text "TEXAS INSTRUMENTS" at 5113,-1064.34 h60
M6 Assembly Bottom:
  lines w10: -292.5,-727.33 6309.5,-727.33 ; -290.5,-930.67 6309.5,-930.67 ; 1115.5,-1140.5 1115.5,-937.67 ; 1737.5,-727.33 1737.5,-524 ; 2577.5,-727.33 2577.5,-524 ; 3844.5,-1134 3844.5,-524 ; 4733.5,-1134 6309,-1134 6309,-524 -292.5,-524 -292.5,-1134 2304.5,-1134 6309.5,-1134 6309.5,-524
  text "COMPONENTS MARKED 'DNP' SHOULD NOT BE POPULATED." at 6102,-318 h60
  text ".VariantName" at 5058,-434 h60
  text "ASSEMBLY VARIANT:" at 6097,-434 h60
  text ".VersionControl_RevNumber" at 1035.5,-656.17 h60
  text "SVN REV:" at 1541.5,-656.17 h60
  text ".PCB_Rev" at 2088,-656.17 h60
  text "REV:" at 2379.5,-656.17 h60
  text ".PRJ_Number" at 3224,-656.17 h60
  text "BOARD #:" at 3769.5,-656.17 h60
  text "PCB VIEWED FROM BOTTOM SIDE" at 6246,-656.17 h60
  text "TEXAS INSTRUMENTS" at 904.5,-1064.84 h60
  text ".Print_Time" at 2169,-1064.84 h60
  text ".Print_Date" at 2898,-1064.84 h60
  text "GENERATED    :" at 3767.5,-1064.84 h60
  text ".plot_File_Name" at 5440.5,-1064.84 h60
  text "PLOT NAME =" at 6246,-1064.84 h60
M9 Title Sheet:
  drawing of 57 lines, arcs and shapes, not listed
  text "1" at 739.84,8036.5 h70
  text "2" at 3235.5,8036.5 h70
  text "3" at 5724.84,8036.5 h70
  text "4" at 8231.51,8036.5 h70
  text "5" at 10730.5,8036.5 h70
  text "6" at 13235.5,8036.5 h70
  text "A" at -416.5,6893.5 h70
  text "A" at 14383.5,6893.5 h70
  text "B" at -416.5,4513.5 h70
  text "B" at 14383.5,4513.5 h70
  text "C" at -416.5,2138.5 h70
  text "C" at 14383.5,2138.5 h70
  text "PROJECT TITLE:" at 11343.5,277.5 h45
  text ".PRJ_Title" at 11393.5,144.17 h70
  text "DESIGNED FOR:" at 11343.5,-23.5 h45
  text ".PRJ_Customer" at 11393.5,-163.5 h70
  text "D" at -416.5,-231.5 h70
  text "D" at 14383.5,-231.5 h70
  text "FILE NAME:" at 11343.5,-323.5 h45
  text ".PCB_File_Name_No_Path" at 11393.5,-443.5 h70
  text "Texas Instruments (TI) and/or its licensors do not warrant the accuracy or completeness of this specification" at 6374,-605.34 h45
  text "ENGINEER:" at 11343.5,-613.5 h45
  text "LAYOUT BY:" at 12848.5,-613.5 h45
  text "or any information contained therein. TI and/or its licensors do not warrant that this design will meet" at 6329.01,-718 h45
  text ".PRJ_Engineer" at 11393.5,-768.49 h70
  text ".PCB_Layout" at 12899,-768.49 h70
  text "the specifications, will be suitable for your application or fit for any particular purpose, or will operate in" at 6329.01,-830.67 h45
  text ".Layer_Name" at 577,-858.49 h60
  text "ALTIUM DESIGNER VERSION:" at 12848.5,-923.5 h45
  text "an implementation. TI and/or its licensors do not warrant that the design is production worthy. You should" at 6329.01,-943.33 h45
  text "completely validate and test your design implementation to confirm the system functionality for your application." at 6374,-1056 h45
  text ".print_Scale" at 11393.5,-1056.83 h70
  text ".Application_BuildNumber" at 12899,-1056.83 h70
  text "1" at 739.84,-1263.5 h70
  text "2" at 3235.5,-1263.5 h70
  text "3" at 5724.84,-1263.5 h70
  text "4" at 8231.51,-1263.5 h70
  text "5" at 10730.5,-1263.5 h70
  text "6" at 13235.5,-1263.5 h70
M10 Fab Notes:
  drawing of 185 lines, arcs and shapes, not listed
  text "DESIGN INFORMATION" at 12381.02,5910 h60
  text "MIN. TRACK WIDTH:" at 11736.46,5730 h60
  text "8" at 12832.7,5730 h60
  text "MIL" at 12987.46,5730 h60
  text "MIN. CLEARANCE:" at 11736.46,5598 h60
  text "0.2" at 12772.7,5598 h60
  text "mm" at 12987.46,5598 h60
  text "MIN. VIA PAD SIZE:" at 11736.46,5466 h60
  text "24" at 12802.71,5466 h60
  text "MIL" at 12987.46,5466 h60
  text "0.05mm (2MIL)" at 12431.46,5324.29 h60
  text "MINIMUM ANNULAR RING" at 11407.23,5320 h60
  text "EXTERNAL" at 13139.46,5320 h60
  text "PER" at 11607.23,5202 h60
  text "IPC-D-275 CLASS 2 LEVEL C" at 11827.23,5202 h60
  text "MIL, HOLES" at 13315.46,5089.71 h60
  text "+/-" at 12923,5089 h60
  text "+/-" at 13777,5089 h60
  text "REGISTRATION TOLERANCES:" at 11407.23,5084 h60
  text "METAL" at 12607,5084 h60
  text "5" at 13183.2,5084 h60
  text "3" at 14016.2,5084 h60
  text "MIL" at 14132.46,5084 h60
  text "MATERIAL:" at 11332.46,4874.54 h60
  text "FR-4 High Tg" at 12318.9,4734.21 h60
  text "FR-408" at 11753.46,4725.64 h60
  text "X" at 12165.46,4725.64 h60
  text "OTHER" at 13241.46,4725.64 h60
  text "62 MIL (1.6mm) +/-10%" at 12073.56,4562.92 h60
  text "THICKNESS:" at 11407.23,4558.64 h60
  text "X" at 11945.4,4558.64 h60
  text "OTHER" at 13358.46,4558.64 h60
  text "TOLERANCE:" at 11407.23,4400.64 h60
  text "X" at 12246.53,4400.64 h60
  text "ANSI IPC-6012 TYPE 3 CLASS 2" at 12433.48,4400.64 h60
  text "OTHER +/-" at 12433.46,4244.64 h60
  text "BOW & TWIST:" at 11407.23,4087.64 h60
  text "X" at 12246.53,4087.64 h60
  text "ANSI IPC-6012 TYPE 3 CLASS 2" at 12433.48,4087.64 h60
  text "OTHER +/-" at 12433.46,3929.13 h60
  text "DRILLING:" at 11332.46,3790.64 h60
  text "REFERENCE:" at 11407.23,3673.64 h60
  text "X" at 12055.46,3673.64 h60
  text "AS SHOWN" at 12242.46,3673.64 h60
  text "X" at 12956.46,3673.64 h60
  text "NC_DRILL FILES" at 13093.46,3673.64 h60
  text "PTH MIN COPPER THICKNESS:" at 11407.23,3515.64 h60
  text "X" at 12757.46,3515.64 h60
  text "1MIL" at 12894.46,3515.64 h60
  text "OTHER" at 13391.46,3515.64 h60
  text "BOARD FINISH:" at 11332.46,3356.64 h60
  text "SILKSCREEN:" at 11487.68,3238.64 h60
  text "X" at 12436.46,3238.64 h60
  text "TOP" at 12562.46,3238.64 h60
  text "X" at 12946.46,3238.64 h60
  text "BOTTOM" at 13073.46,3238.64 h60
  text "SILKSCREEN COLOR:" at 11487.68,3071.64 h60
  text "X" at 12435.42,3071.64 h60
  text "WHITE" at 12562.46,3071.64 h60
  text "OTHER" at 13073.46,3071.64 h60
  text "SOLDER RESIST COLOR:" at 11487.68,2901.64 h60
  text "GREEN" at 12182.46,2742.44 h60
  text "BLUE" at 12773.46,2742.44 h60
  text "OTHER" at 13311.46,2742.44 h60
  text "X" at 12645,2740 h60
  text "IMMERSION GOLD (ENIG)" at 12393.46,2553.92 h60
  text "ENEPIG" at 13731,2550.64 h60
  text "SURFACE FINISH:" at 11332.46,2549.64 h60
  text "IMM. TIN/SILVER OR EQUIV" at 11662,2392.64 h60
  text "OTHER" at 13093.46,2392.64 h60
  text "X" at 11500,2390 h60
  text "ARRAY/PANEL:" at 11332.46,2213.64 h60
  text "CUT AND TRIM PER MECH LAYER 1" at 12393.46,2209.35 h60
  text "N.C. ROUTE" at 12393.46,2057.64 h60
  text "X" at 13072.46,2057.64 h60
  text "V. SCORE" at 13259.46,2057.64 h60
  text "CERTIFICATION:" at 11332.46,1920.64 h60
  text "MATERIALS AND WORKMANSHIP FOR ALL PCBS" at 12057.46,1920.64 h60
  text "TO MEET OR EXCEED THE REQUIREMENTS OF:" at 12057.46,1822.64 h60
  text "X" at 11683.96,1686.13 h60
  text "ANSI IPC-A-600F CLASS ->" at 11822.96,1686.13 h60
  text "X" at 13462.02,1686.13 h60
  text "2" at 13580.96,1686.14 h60
  text "1" at 13265.96,1684.64 h60
  text "3" at 13934.96,1684.64 h60
  text "X" at 11686.02,1526.64 h60
  text "UL 94V-0" at 11822.96,1526.64 h60
  text "X" at 12498.02,1526.64 h60
  text "RoHS" at 12634.96,1526.64 h60
  text "OTHER" at 13279.36,1526.64 h60
  text "PER ORDER" at 13676.42,1526.64 h60
  text "ADDITIONAL REQUIREMENTS:" at 11332.46,1385.64 h60
  text "MICROSECTION:" at 11407.23,1270.64 h60
  text "YES" at 12312.96,1270.64 h60
  text "REQUIRED" at 13174.46,1114.49 h60
  text "BARE BOARD ELEC. TEST:" at 11407.23,1111.64 h60
  text "NONE" at 12712.96,1111.64 h60
  text "X" at 13047.46,1111.64 h60
  text "PER ORDER" at 13766.46,1111.64 h60
  text "MANUFACTURER'S UL:" at 11407.23,954.64 h60
  text "RAIL" at 12572.96,950.35 h60
  text "METAL" at 13064.77,950.35 h60
  text "X" at 13440,950 h60
  text "SILK" at 13576.46,950.35 h60
  text ".Layer_Name" at 577,-858.49 h60
M11 Gerber Information:
  lines w10: -292,-930.17 6308,-930.17 ; -292,-726.83 6310,-726.83 ; -292,-523.5 -292,-1133.5 3713,-1133.5 6310,-1133.5 6310,-523.5 -291.5,-523.5 -291.5,-1133.5 1284,-1133.5 ; 2173,-1133.5 2173,-523.5 ; 3440,-726.83 3440,-523.5 ; 4280,-726.83 4280,-523.5 ; 4902,-1140 4902,-937.17
  text "ALL ARTWORK VIEWED FROM TOP SIDE" at -228.5,-655.67 h60
  text "BOARD #:" at 2248,-655.67 h60
  text ".PRJ_Number" at 2793.5,-655.67 h60
  text "REV:" at 3638,-655.67 h60
  text ".PCB_Rev" at 3929.5,-655.67 h60
  text "SVN REV:" at 4476,-655.67 h60
  text ".VersionControl_RevNumber" at 4982,-655.67 h60
  text "LAYER NAME =" at -228.5,-858.49 h60
  text "PLOT NAME =" at -228.5,-1064.34 h60
  text ".plot_File_Name" at 577,-1064.34 h60
  text "GENERATED    :" at 2250,-1064.34 h60
  text ".Print_Date" at 3119.5,-1064.34 h60
  text ".Print_Time" at 3848.5,-1064.34 h60
  text "TEXAS INSTRUMENTS" at 5113,-1064.34 h60
M12 Stackup:
  drawing of 295 lines, arcs and shapes, not listed
  text "Layer" at 9750.35,7800 h60
  text "Name" at 10160.26,7800 h60
  text "Material" at 11100,7800 h60
  text "Thickness" at 11959.77,7800 h60
  text "Constant" at 12609.6,7800 h60
  text "Board Layer Stack" at 13179.46,7800 h60
  text "1" at 9750.35,7680 h60
  text "Top Overlay" at 10160.26,7680 h60
  text "2" at 9750.35,7560 h60
  text "Top Solder" at 10160.26,7560 h60
  text "Solder Resist" at 11100,7560 h60
  text "0.40mil" at 11959.77,7560 h60
  text "3.5" at 12609.6,7560 h60
  text "3" at 9750.35,7440 h60
  text "Top Layer" at 10160.26,7440 h60
  text "Copper" at 11100,7440 h60
  text "2.80mil" at 11959.77,7440 h60
  text "4" at 9750.35,7320 h60
  text "Dielectric1" at 10160.26,7320 h60
  text "FR-4" at 11100,7320 h60
  text "59.20mil" at 11959.77,7320 h60
  text "4.8" at 12609.6,7320 h60
  text "5" at 9750.35,7200 h60
  text "Signal Layer 1" at 10160.26,7200 h60
  text "Copper" at 11100,7200 h60
  text "2.80mil" at 11959.77,7200 h60
  text "6" at 9750.35,7080 h60
  text "Dielectric 3" at 10160.26,7080 h60
  text "5.00mil" at 11959.77,7080 h60
  text "4.2" at 12609.6,7080 h60
  text "7" at 9750.35,6960 h60
  text "Signal Layer 2" at 10160.26,6960 h60
  text "Copper" at 11100,6960 h60
  text "2.80mil" at 11959.77,6960 h60
  text "8" at 9750.35,6840 h60
  text "Dielectric 2" at 10160.26,6840 h60
  text "10.00mil" at 11959.77,6840 h60
  text "4.2" at 12609.6,6840 h60
  text "9" at 9750.35,6720 h60
  text "Bottom Layer" at 10160.26,6720 h60
  text "Copper" at 11100,6720 h60
  text "2.80mil" at 11959.77,6720 h60
  text "10" at 9750.35,6600 h60
  text "Bottom Solder" at 10160.26,6600 h60
  text "Solder Resist" at 11100,6600 h60
  text "0.40mil" at 11959.77,6600 h60
  text "3.5" at 12609.6,6600 h60
  text "11" at 9750.35,6480 h60
  text "Bottom Overlay" at 10160.26,6480 h60
  text ".Layer_Name" at 577,-858.49 h60
M13 Component Bodies Top:
  text ".Layer_Name" at 577,-858.49 h60
M14 Component Bodies Bottom:
  text ".Layer_Name" at 577,-858.49 h60
M15 Courtyards Top:
  text ".Layer_Name" at 577,-858.49 h60
M16 Courtyards Bottom:
  text ".Layer_Name" at 577,-858.49 h60
Drill Drawing:
  circle w1: c5572.72,3221.04 r24.89
  lines w1: 5547.83,2797.97 5597.6,2797.97 5572.72,2748.2 5547.83,2797.97 ; 5547.83,2897.52 5597.6,2897.52 5597.6,2947.29 5547.83,2947.29 5547.83,2897.52 ; 5547.83,3046.84 5572.72,3059.28 5597.6,3046.84 5585.16,3071.72 5597.6,3096.61 5572.72,3084.17 5547.83,3096.61 5560.27,3071.72 5547.83,3046.84
  lines w12: 5480,2703.4 7598.02,2703.4 ; 5480,3300.68 7598.02,3300.68 ; 5850.36,2554.08 5850.36,3450 ; 6207.36,2554.08 6207.36,3450 ; 6868.93,2554.08 6868.93,3450 ; 7153.07,2554.08 7153.07,3450 ; 5480,2554.08 7598.02,2554.08 7598.02,3450 5480,3450 5480,2554.08
  text "Symbol" at 5569.59,3345.48 h72
  text "Quantity" at 5895.16,3345.48 h72
  text "Finished Hole Size" at 6252.16,3345.48 h72
  text "Plated" at 6913.72,3345.48 h72
  text "Hole Type" at 7197.86,3345.48 h72
  text "4" at 5895.16,3196.16 h60
  text "7.87mil (0.200mm)" at 6252.16,3196.16 h60
  text "PTH" at 6913.72,3196.16 h60
  text "Round" at 7197.86,3196.16 h60
  text "61" at 5895.16,3046.84 h60
  text "16.00mil (0.406mm)" at 6252.16,3046.84 h60
  text "PTH" at 6913.72,3046.84 h60
  text "Round" at 7197.86,3046.84 h60
  text "12" at 5895.16,2897.52 h60
  text "40.00mil (1.016mm)" at 6252.16,2897.52 h60
  text "PTH" at 6913.72,2897.52 h60
  text "Round" at 7197.86,2897.52 h60
  text "4" at 5895.16,2748.2 h60
  text "50.00mil (1.270mm)" at 6252.16,2748.2 h60
  text "PTH" at 6913.72,2748.2 h60
  text "Round" at 7197.86,2748.2 h60
  text "81 Total" at 5895.16,2598.88 h60
  text ".Layer_Name" at 577,-858.49 h60

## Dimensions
0,-400 to 1000,-400 on M2 Board Dimensions
0,0 to 0,1968.5 on M2 Board Dimensions
0,0 to 1968.5,0 on M2 Board Dimensions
